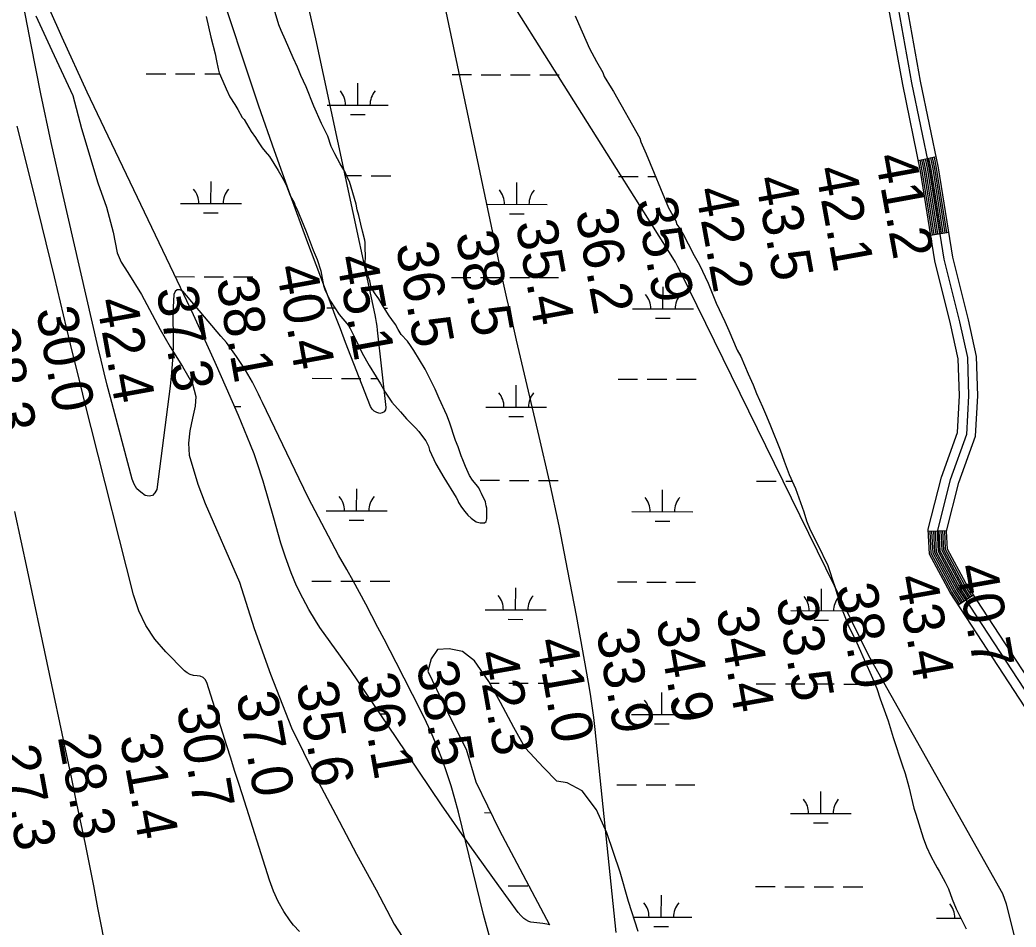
# Model space of a CAD drawing. Extents: x 3161665 to 3199565, y 885729 to 911164.
# Drawn here: x 3179018 to 3180653, y 894492 to 895980 of the extents above; entities that cross this region are included whole.
import ezdxf

# ---------------------------------------------------------------- set-up
doc = ezdxf.new("R2010")
doc.units = 0
for name, color, linetype in [('V-RIVR-RANG', 7, 'Continuous'), ('V-ROAD-CNTR', 7, 'Continuous'), ('V-SITE-VEGE', 7, 'Continuous'), ('V-TOPO-MAJR', 7, 'Continuous'), ('V-TOPO-MINR', 7, 'Continuous'), ('V-WETL-SWMP', 7, 'Continuous')]:
    doc.layers.add(name, color=color, linetype=linetype)

msp = doc.modelspace()

# ---------------------------------------------------------------- linework, layer by layer
at = {"layer": 'V-ROAD-CNTR'}
for p, q in [((3180492, 895749.5), (3180521.4, 895755.6)), ((3180512.4, 895626.9), (3180542, 895631.6)), ((3180508.4, 895141), (3180538.4, 895142.5)), ((3180557.4, 895020.5), (3180582.5, 895036.9))]:
    msp.add_line(p, q, dxfattribs=at)
for points in [[(3180933.2, 894493.7), (3180885, 894517.3), (3180701.9, 894799.4), (3180544.2, 895040.5), (3180510.3, 895103.5), (3180508.3, 895144.3), (3180530.1, 895229.9), (3180556.2, 895302.9), (3180559.6, 895363.6), (3180557.6, 895424.1), (3180545.1, 895481.1), (3180519.1, 895584.7), (3180495.6, 895731.9), (3180466.5, 895873.8), (3180444.2, 895996), (3180423.4, 896082.2), (3180408.8, 896168.2), (3180409.7, 896218.8), (3180409.8, 896281.3), (3180411, 896343.4), (3180408.4, 896411.6), (3180401.9, 896523.4)], [(3180416.8, 896524.3), (3180423.3, 896412.3), (3180426, 896343.5), (3180424.8, 896281.2), (3180424.7, 896218.6), (3180423.8, 896169.3), (3180438.1, 896085.2), (3180458.9, 895999.1), (3180481.2, 895876.7), (3180510.4, 895734.6), (3180533.8, 895587.7), (3180559.7, 895484.6), (3180572.6, 895426), (3180574.6, 895363.4), (3180571, 895299.9), (3180544.5, 895225.5), (3180523.4, 895142.8), (3180525.2, 895107.6), (3180557.1, 895048.2), (3180714.5, 894807.5), (3180895.4, 894528.9), (3180947.4, 894503.4), (3180964.9, 894492.4)], [(3180963.3, 894511.2), (3180954.7, 894516.5), (3180905.7, 894540.6), (3180727, 894815.7), (3180570.1, 895055.9), (3180540, 895111.8), (3180538.5, 895141.2), (3180558.9, 895221.1), (3180585.9, 895296.9), (3180589.7, 895363.3), (3180587.5, 895427.9), (3180574.3, 895488), (3180548.6, 895590.7), (3180525.2, 895737.3), (3180495.9, 895879.6), (3180473.6, 896002.2), (3180452.8, 896088.2), (3180438.9, 896170.4), (3180439.7, 896218.5), (3180439.8, 896281), (3180441, 896343.7), (3180438.3, 896413.1), (3180431.8, 896525.1)], [(3180515.4, 895627.4), (3180498.6, 895732.4), (3180495, 895750.1)], [(3180518.3, 895627.8), (3180501.5, 895733), (3180497.9, 895750.7)], [(3180521.3, 895628.3), (3180504.5, 895733.5), (3180500.8, 895751.3)], [(3180524.3, 895628.8), (3180507.5, 895734), (3180503.8, 895751.9)], [(3180527.2, 895629.3), (3180510.4, 895734.6), (3180506.7, 895752.5)], [(3180530.2, 895629.7), (3180513.4, 895735.1), (3180509.6, 895753.2)], [(3180533.1, 895630.2), (3180516.3, 895735.6), (3180512.6, 895753.8)], [(3180536.1, 895630.7), (3180519.3, 895736.2), (3180515.5, 895754.4)], [(3180539.1, 895631.1), (3180522.2, 895736.7), (3180518.5, 895755)], [(3180559.9, 895022.1), (3180546.8, 895042.1), (3180513.3, 895104.3), (3180511.4, 895141.1)], [(3180562.4, 895023.7), (3180549.4, 895043.6), (3180516.3, 895105.2), (3180514.4, 895141.3)], [(3180564.9, 895025.4), (3180552, 895045.1), (3180519.2, 895106), (3180517.4, 895141.5)], [(3180567.4, 895027), (3180554.6, 895046.7), (3180522.2, 895106.8), (3180520.4, 895141.6)], [(3180569.9, 895028.7), (3180557.1, 895048.2), (3180525.2, 895107.6), (3180523.4, 895141.8)], [(3180572.4, 895030.3), (3180559.7, 895049.8), (3180528.1, 895108.5), (3180526.4, 895141.9)], [(3180574.9, 895032), (3180562.3, 895051.3), (3180531.1, 895109.3), (3180529.4, 895142.1)], [(3180577.5, 895033.6), (3180564.9, 895052.8), (3180534, 895110.1), (3180532.4, 895142.2)], [(3180580, 895035.2), (3180567.5, 895054.4), (3180537, 895111), (3180535.4, 895142.4)]]:
    msp.add_lwpolyline(points, dxfattribs=at)
at = {"layer": 'V-SITE-VEGE'}
for p, q in [((3179043.8, 895986.4), (3179069.8, 895930)), ((3179069.8, 895930), (3179104.5, 895856.2)), ((3179104.5, 895856.2), (3179118.6, 895801.9)), ((3179118.6, 895801.9), (3179145.7, 895712.9)), ((3179145.7, 895712.9), (3179159.8, 895672.8)), ((3179159.8, 895672.8), (3179170.7, 895631.6)), ((3179170.7, 895631.6), (3179177.2, 895597.9)), ((3179177.2, 895597.9), (3179183.7, 895582.7)), ((3179183.7, 895582.7), (3179194.6, 895565.4)), ((3179194.6, 895565.4), (3179217.3, 895529.5)), ((3179217.3, 895529.5), (3179247.7, 895472)), ((3179247.7, 895472), (3179264, 895443.8)), ((3179264, 895443.8), (3179284.6, 895411.3)), ((3179284.6, 895411.3), (3179300.9, 895383.1)), ((3179300.9, 895383.1), (3179306.3, 895362.4)), ((3179306.3, 895362.4), (3179305.2, 895346.2)), ((3179305.2, 895346.2), (3179300.9, 895326.6)), ((3179300.9, 895326.6), (3179296.5, 895306)), ((3179296.5, 895306), (3179294.4, 895285.4)), ((3179294.4, 895285.4), (3179295.4, 895265.9)), ((3179295.4, 895265.9), (3179309.5, 895218.1)), ((3179309.5, 895218.1), (3179321.5, 895186.7)), ((3179321.5, 895186.7), (3179377.9, 895057.5)), ((3179377.9, 895057.5), (3179401.8, 894981.6)), ((3179401.8, 894981.6), (3179428.9, 894906.7)), ((3179428.9, 894906.7), (3179463.6, 894818.8)), ((3179463.6, 894818.8), (3179502.6, 894738.5)), ((3179502.6, 894738.5), (3179536.3, 894675.6)), ((3179536.3, 894675.6), (3179569.9, 894611.5)), ((3179569.9, 894611.5), (3179602.4, 894552.9)), ((3179602.4, 894552.9), (3179631.7, 894496.5)), ((3179631.7, 894496.5), (3179663.2, 894448.8))]:
    msp.add_line(p, q, dxfattribs=at)
at = {"layer": 'V-TOPO-MAJR'}
for points in [[(3179681.7, 896160.1), (3179801.4, 895592.2), (3179808.8, 895557.7), (3179816.4, 895523.4), (3179824.2, 895489), (3179832.1, 895454.7), (3179869.5, 895296.7), (3179886.1, 895223.5), (3179902, 895150.1), (3179916.6, 895076.4), (3179930.5, 895002.6), (3179950.1, 894893), (3179953.4, 894873.8), (3179956.3, 894854.6), (3179958.8, 894835.4), (3179961, 894816.1), (3179995.6, 894482.6)], [(3180681.8, 894350.6), (3180637, 894529.1), (3180631.1, 894546.5), (3180410.8, 894936.6), (3180101, 895567.5), (3180097.6, 895575.1), (3180093.7, 895582.5), (3180089.4, 895589.8), (3179777.1, 896084.7)], [(3179787.8, 894478.3), (3179778.7, 894512.5), (3179737.3, 894680.3), (3179731.5, 894701.9), (3179725.3, 894723.3), (3179718.3, 894744.6), (3179710.9, 894765.6), (3179702.7, 894786.4), (3179694, 894807), (3179684.7, 894827.3), (3179674.9, 894847.4), (3179634.9, 894925.9), (3179625, 894945.1), (3179615.2, 894964.3), (3179605.2, 894983.4), (3179595.2, 895002.5), (3179585.1, 895021.6), (3179574.8, 895040.6), (3179564.5, 895059.5), (3179554, 895078.4), (3179540.7, 895102.1), (3179523.8, 895133), (3179507.4, 895164), (3179491.4, 895195.4), (3179475.9, 895226.9), (3179415.6, 895352.3), (3179412.4, 895359), (3179409.2, 895365.7), (3179405.9, 895372.5), (3179402.6, 895379.2), (3179399.2, 895385.8), (3179395.7, 895392.4), (3179391.9, 895398.8), (3179388, 895405.2), (3179380.9, 895416.3), (3179373.1, 895427.9), (3179365, 895439.4), (3179356.5, 895450.5), (3179347.6, 895461.3), (3179285, 895534.7), (3179280.1, 895537), (3179275.8, 895537.3), (3179272.5, 895534.5), (3179270, 895529.7), (3179269.4, 895519.3), (3179269, 895508.8), (3179268.8, 895498.3), (3179268.8, 895487.8), (3179269.1, 895465.5), (3179269, 895443.8), (3179268.2, 895422.2), (3179266.5, 895400.7), (3179264.1, 895379.2), (3179242.1, 895209.8), (3179239.2, 895203.9), (3179235.2, 895199.9), (3179229.7, 895198.9), (3179223.1, 895199.9), (3179215.8, 895205), (3179209.6, 895210.9), (3179205.1, 895218.3), (3179201.8, 895226.5), (3179166.3, 895360.3), (3179161, 895380.7), (3179155.9, 895401.1), (3179150.9, 895421.5), (3179146.1, 895442), (3179086.8, 895699.1), (3179069, 895778.8), (3179052, 895858.7), (3179036, 895938.8), (3179020.7, 896019.1)]]:
    msp.add_lwpolyline(points, dxfattribs=at)
at = {"layer": 'V-TOPO-MINR'}
for points in [[(3179490.3, 896004.2), (3179502.5, 895948.9), (3179600.1, 895496.3), (3179601.3, 895490), (3179602.4, 895483.7), (3179603.3, 895477.4), (3179604.1, 895471.1), (3179618.2, 895344.3), (3179617.4, 895340.2), (3179615.6, 895337), (3179612.4, 895335.2), (3179608.3, 895334.4), (3179603.4, 895335.8), (3179599.2, 895338), (3179595.9, 895341.5), (3179593.2, 895345.9), (3179560.8, 895428.5), (3179552.2, 895450.7), (3179543.6, 895472.9), (3179535.1, 895495.1), (3179526.7, 895517.3), (3179488.6, 895618.6), (3179461.7, 895691.7), (3179435.3, 895765), (3179409.9, 895838.6), (3179385, 895912.4), (3179295.6, 896183.8)], [(3179476.3, 894484.6), (3179466.5, 894495.1), (3179461.4, 894501.9), (3179450.9, 894517.5), (3179441.5, 894533.7), (3179433.8, 894550.8), (3179427.2, 894568.5), (3179382.7, 894708.6), (3179376.3, 894728.7), (3179369.9, 894748.8), (3179363.5, 894769), (3179357.1, 894789.1), (3179324.1, 894893), (3179321.4, 894897.6), (3179318.1, 894901.2), (3179313.6, 894903.1), (3179308.4, 894904.1), (3179302.6, 894904.6), (3179297.2, 894906), (3179292.3, 894908.7), (3179287.8, 894912.2), (3179256.9, 894943.1), (3179239.2, 894963.9), (3179224, 894986.2), (3179212.6, 895010.7), (3179203.8, 895036.6), (3179134.5, 895311.4), (3179124.2, 895352.3), (3179114, 895393.3), (3179104, 895434.4), (3179094.1, 895475.4), (3179074.1, 895558.3), (3179054.1, 895640.8), (3179033.8, 895723.2), (3179013.1, 895805.5)], [(3179306.3, 893574), (3179246.9, 893954.3), (3179241.4, 893988.3), (3179235.9, 894022.2), (3179230, 894056.1), (3179224, 894089.9), (3179152.3, 894487.5), (3179145.6, 894523.4), (3179138.8, 894559.1), (3179131.7, 894594.9), (3179124.5, 894630.6), (3179117, 894666.2), (3179109.6, 894701.9), (3179102.1, 894737.5), (3179094.5, 894773.2), (3179030.2, 895077.4), (3179019.8, 895125.6), (3179009.2, 895173.7)]]:
    msp.add_lwpolyline(points, dxfattribs=at)
at = {"layer": 'V-WETL-SWMP'}
for p, q in [((3179224.9, 895891.6), (3179256.9, 895891.5)), ((3179272.9, 895891.5), (3179304.9, 895891.4)), ((3179320.9, 895891.4), (3179345.5, 895891.3)), ((3179726.8, 895890.2), (3179758.8, 895890.2)), ((3179774.8, 895890.1), (3179806.8, 895890)), ((3179822.8, 895890), (3179854.8, 895889.9)), ((3179870.8, 895889.9), (3179902.8, 895889.8)), ((3179572, 895839.9), (3179572.1, 895875.9)), ((3179522, 895840.1), (3179622, 895839.8)), ((3179560, 895824.5), (3179584, 895824.5)), ((3179554, 895724.6), (3179578.3, 895724.5)), ((3179594.3, 895724.4), (3179626.3, 895724.4)), ((3180000.2, 895723.3), (3180032.2, 895723.2)), ((3180048.2, 895723.2), (3180060.9, 895723.2)), ((3179331.1, 895678.7), (3179331.2, 895714.7)), ((3179833, 895677.4), (3179833.1, 895713.4)), ((3179281.1, 895678.9), (3179381.1, 895678.6)), ((3179783, 895677.5), (3179883, 895677.2)), ((3179319.1, 895663.3), (3179343.1, 895663.3)), ((3179821, 895662), (3179845, 895661.9)), ((3179272.9, 895558.8), (3179303.9, 895558.7)), ((3179319.9, 895558.7), (3179351.9, 895558.6)), ((3179367.9, 895558.6), (3179399.9, 895558.5)), ((3179725.8, 895557.6), (3179757.8, 895557.5)), ((3179773.8, 895557.4), (3179805.8, 895557.4)), ((3179821.8, 895557.3), (3179853.8, 895557.2)), ((3179869.8, 895557.2), (3179901.8, 895557.1)), ((3180073, 895505.9), (3180073.1, 895541.9)), ((3179521.1, 895507.4), (3179534.4, 895507.4)), ((3179615.6, 895507.1), (3179621.1, 895507.1)), ((3180023, 895506), (3180123, 895505.7)), ((3180061, 895490.5), (3180085, 895490.4)), ((3179497.4, 895392), (3179529.4, 895391.9)), ((3179545.4, 895391.9), (3179577.4, 895391.8)), ((3179593.4, 895391.8), (3179603.8, 895391.7)), ((3179999.3, 895390.6), (3180031.3, 895390.6)), ((3180047.3, 895390.5), (3180079.3, 895390.4)), ((3180095.3, 895390.4), (3180127.3, 895390.3)), ((3179832.1, 895344.7), (3179832.2, 895380.7)), ((3179369.7, 895346), (3179380.2, 895345.9)), ((3179782.1, 895344.8), (3179882.1, 895344.5)), ((3179820.1, 895329.3), (3179844.1, 895329.2)), ((3179570.2, 895174.6), (3179570.3, 895210.6)), ((3179772.9, 895224.8), (3179804.9, 895224.7)), ((3179820.9, 895224.6), (3179852.9, 895224.5)), ((3179868.9, 895224.5), (3179900.9, 895224.4)), ((3180226.8, 895223.5), (3180258.8, 895223.4)), ((3180274.8, 895223.4), (3180285.1, 895223.4)), ((3180072.1, 895173.2), (3180072.2, 895209.2)), ((3179520.2, 895174.7), (3179620.2, 895174.4)), ((3180022.1, 895173.3), (3180122.1, 895173.1)), ((3179558.1, 895159.2), (3179582.1, 895159.1)), ((3180060.1, 895157.8), (3180084.1, 895157.7)), ((3179496.5, 895059.4), (3179528.5, 895059.3)), ((3179544.5, 895059.2), (3179576.5, 895059.1)), ((3179592.5, 895059.1), (3179624.5, 895059)), ((3179831.2, 895012), (3179831.3, 895048)), ((3179998.4, 895058), (3180030.4, 895057.9)), ((3180046.4, 895057.8), (3180078.4, 895057.8)), ((3180094.4, 895057.7), (3180126.4, 895057.6)), ((3180333.1, 895010.6), (3180333.2, 895046.6)), ((3179781.2, 895012.1), (3179881.2, 895011.9)), ((3180283.1, 895010.8), (3180367.6, 895010.5)), ((3179819.1, 894996.6), (3179843.1, 894996.5)), ((3180321, 894995.2), (3180345, 894995.2)), ((3179788.7, 894892), (3179804, 894892)), ((3179820, 894892), (3179852, 894891.9)), ((3179868, 894891.8), (3179900, 894891.7)), ((3180225.9, 894890.8), (3180257.9, 894890.8)), ((3180273.9, 894890.7), (3180305.9, 894890.6)), ((3180321.9, 894890.6), (3180353.9, 894890.5)), ((3180369.9, 894890.4), (3180401.9, 894890.4)), ((3180071.2, 894840.5), (3180071.3, 894876.5)), ((3179608.7, 894841.8), (3179619.3, 894841.8)), ((3180021.2, 894840.7), (3180121.2, 894840.4)), ((3180059.1, 894825.1), (3180083.1, 894825.1)), ((3179997.5, 894725.3), (3180029.5, 894725.2)), ((3180045.5, 894725.2), (3180077.5, 894725.1)), ((3180093.5, 894725), (3180125.5, 894724.9)), ((3180332.2, 894677.9), (3180332.3, 894713.9)), ((3179780.3, 894679.5), (3179790.7, 894679.4)), ((3180282.2, 894678.1), (3180382.2, 894677.8)), ((3180320.1, 894662.5), (3180344.1, 894662.5)), ((3179819.1, 894559.3), (3179851.1, 894559.2)), ((3180225, 894558.2), (3180257, 894558.1)), ((3180273, 894558), (3180305, 894557.9)), ((3180321, 894557.9), (3180353, 894557.8)), ((3180369, 894557.8), (3180401, 894557.7)), ((3180070.3, 894507.9), (3180070.4, 894543.9)), ((3180024.9, 894508), (3180120.3, 894507.7)), ((3180522.2, 894506.6), (3180562, 894506.5)), ((3180058.2, 894492.5), (3180082.2, 894492.4))]:
    msp.add_line(p, q, dxfattribs=at)
for points in [[(3179780, 895155), (3179782.6, 895156.9), (3179783.9, 895161.4), (3179784, 895178.9), (3179782.8, 895182.8), (3179781.5, 895189.3), (3179775.1, 895203), (3179773.2, 895207.5), (3179770.7, 895212.1), (3179766.2, 895217.9), (3179760.4, 895225.1), (3179755.3, 895232.3), (3179748.9, 895247.2), (3179744.5, 895258.3), (3179741.9, 895264.8), (3179736.8, 895279.7), (3179732.4, 895290.1), (3179722.9, 895320), (3179718.4, 895331.7), (3179705.7, 895359), (3179699.3, 895374), (3179682.7, 895407.2), (3179664.1, 895437.8), (3179658.4, 895445.6), (3179653.9, 895452.7), (3179643.6, 895463.8), (3179638.5, 895472.3), (3179634, 895480.1), (3179628.2, 895488.6), (3179623.7, 895494.4), (3179614.1, 895509.4), (3179606.4, 895522.4), (3179603.9, 895526.3), (3179600.7, 895530.3), (3179596.8, 895536.8), (3179593.6, 895543.9), (3179591.8, 895551.7), (3179588.6, 895560.8), (3179584.2, 895580.9), (3179584.2, 895584.8), (3179584.9, 895588.1), (3179585, 895597.1), (3179584.3, 895601), (3179584.4, 895614.6), (3179583.8, 895618.5), (3179580.1, 895633.5), (3179576.9, 895645.1), (3179573.8, 895658.8), (3179571.2, 895668.5), (3179569.4, 895677.6), (3179558.6, 895714.6), (3179555.4, 895721.1), (3179551, 895731.5), (3179543.3, 895743.9), (3179534.3, 895760.2), (3179528.6, 895772.5), (3179522.9, 895789.4), (3179512.7, 895810.2), (3179499.9, 895838.2), (3179487.2, 895870.1), (3179478.9, 895888.9), (3179473.2, 895902.6), (3179466.2, 895917.5), (3179453.4, 895946.8), (3179446.4, 895962.4), (3179442.6, 895972.1), (3179423.6, 896036.4)], [(3179560.6, 894912.9), (3179510.1, 894983.1), (3179502.5, 894994.7), (3179492, 895012.7), (3179482, 895031.1), (3179471.8, 895051.8), (3179462.8, 895073), (3179453.3, 895098.8), (3179445.9, 895121.7), (3179434.1, 895162.3), (3179416.8, 895223.2), (3179407.2, 895253.3), (3179401.9, 895268.1), (3179396.1, 895282.8), (3179376.1, 895331), (3179356.8, 895375.9), (3179338.2, 895417.8), (3179302.5, 895496), (3179270.4, 895564.1), (3179156.2, 895801.7), (3179128, 895861.3), (3179086.8, 895951.2), (3179066.8, 895996.4)], [(3179323.4, 895985.3), (3179331, 895951.6), (3179337.9, 895924.3), (3179340.4, 895912.6), (3179342.9, 895899.7), (3179344.8, 895893.2), (3179346.7, 895888), (3179356.3, 895867.1), (3179362, 895853.5), (3179370.3, 895841.1), (3179375.4, 895832.7), (3179382.5, 895819.6), (3179385.7, 895816.4), (3179397.2, 895796.8), (3179404.3, 895787.1), (3179408.8, 895779.9), (3179415.2, 895770.1), (3179420.3, 895764.3), (3179427.4, 895755.8), (3179441.5, 895733), (3179449.8, 895718.7), (3179454.9, 895707.6), (3179461.2, 895692), (3179467.6, 895680.3), (3179469.5, 895675.1), (3179472.1, 895669.9), (3179487.4, 895632.9), (3179498.8, 895602.3), (3179505.2, 895586.7), (3179511.5, 895568.5), (3179515.9, 895544.5), (3179517.8, 895537.4), (3179521.6, 895529.6), (3179527.3, 895518.5), (3179541.4, 895496.4), (3179556.9, 895478.7), (3179559.4, 895473.5), (3179569, 895455.3), (3179579.2, 895433.2), (3179590.7, 895413), (3179602.2, 895394.2), (3179609.3, 895383.1), (3179617, 895369.4), (3179627.9, 895353.1), (3179642, 895336.8), (3179652.3, 895325.7), (3179667.1, 895310.7), (3179672.2, 895304.8), (3179678.6, 895296.4), (3179683.8, 895289.2), (3179688.2, 895280.7), (3179690.1, 895274.2), (3179700.3, 895251.5), (3179713.1, 895229.4), (3179733.6, 895196.2), (3179736.2, 895191.6), (3179737.4, 895188.3), (3179742.6, 895180.5), (3179747.7, 895173.4), (3179752.8, 895167.5), (3179758, 895162.3), (3179766.4, 895156.4), (3179772.8, 895155), (3179780, 895155)], [(3179928.8, 895986.7), (3179934.5, 895974.3), (3179952.3, 895933.3), (3179963.9, 895911.9), (3179974.1, 895893.6), (3179976.6, 895887.1), (3179988.2, 895868.3), (3179992, 895862.4), (3180034.9, 895786.2), (3180036.7, 895779.8), (3180045.7, 895760.2), (3180082, 895671.8), (3180094.1, 895650.4), (3180096, 895644.5), (3180100.5, 895638), (3180103.7, 895632.1), (3180105.6, 895629.5), (3180114.6, 895612.6), (3180124.1, 895593.7), (3180133.1, 895578.1), (3180147.1, 895548.2), (3180160.5, 895515.1), (3180174.5, 895485.1), (3180180.9, 895470.2), (3180194.9, 895438.3), (3180200.7, 895427.9), (3180212.8, 895399.3), (3180221.1, 895381.1), (3180226.8, 895366.8), (3180236.4, 895345.3), (3180242.7, 895329.7), (3180249.7, 895314.1), (3180265.6, 895274.5), (3180272, 895256.3), (3180280.2, 895234.2), (3180290.4, 895211.4), (3180304.4, 895173.1), (3180308.8, 895158.2), (3180314.6, 895143.2), (3180326.7, 895119.8), (3180343.9, 895084.7), (3180347.7, 895073.6), (3180351.5, 895061.3), (3180355.3, 895050.2), (3180358.5, 895039.2), (3180368, 895009.3), (3180377.5, 894985.9), (3180383.3, 894973.5), (3180389.7, 894961.8), (3180394.8, 894949.5), (3180403.1, 894930.6), (3180417.1, 894900.1), (3180424.1, 894883.1), (3180429.8, 894866.3), (3180442.5, 894829.9), (3180450.7, 894802.6), (3180465.9, 894757.8), (3180470.3, 894743.5), (3180476.7, 894722), (3180484.8, 894687), (3180488, 894677.2), (3180500, 894638.3), (3180505.7, 894623.3), (3180512.8, 894608.3), (3180519.8, 894594.7), (3180523, 894588.8), (3180526.2, 894583.6), (3180536.4, 894565.4), (3180541.5, 894554.3), (3180547.9, 894537.4), (3180554.2, 894521.8), (3180563.8, 894503), (3180570.8, 894488.7)], [(3180032.4, 894484.5), (3180016.6, 894533.9), (3180002.7, 894582), (3179981.1, 894646.3), (3179963.9, 894684), (3179940.2, 894715.3), (3179915.7, 894728.4), (3179898.8, 894731.2), (3179877, 894753.4), (3179846.7, 894786), (3179828.2, 894819.2), (3179806.5, 894860.2), (3179787.3, 894894.7), (3179763.6, 894928.5), (3179744.2, 894943.6), (3179722.2, 894948.3), (3179702.8, 894947.1), (3179692.3, 894931.7), (3179686.9, 894911.6), (3179723.3, 894836.8), (3179750.2, 894783.5), (3179766, 894730.2), (3179804.3, 894651.5), (3179886.7, 894495.4), (3179882.4, 894496.5), (3179875.7, 894497.5), (3179855.9, 894500), (3179852.9, 894500.9), (3179847.8, 894503.4), (3179844.4, 894505.9), (3179839.7, 894510.5), (3179835.6, 894515.4), (3179803.4, 894559.4), (3179756, 894625.5), (3179709.7, 894692.3), (3179635.2, 894802.7), (3179560.6, 894912.9)]]:
    msp.add_lwpolyline(points, dxfattribs=at)
for centre, start, end in [((3179516.8, 895840.6), 359.0698, 40.6135), ((3179627.3, 895840.3), 139.0698, 180.6135), ((3179275.9, 895679.4), 359.0698, 40.6135), ((3179386.4, 895679.1), 139.0698, 180.6135), ((3179777.8, 895678), 359.0698, 40.6135), ((3179888.3, 895677.7), 139.0698, 180.6135), ((3180017.8, 895506.5), 359.0698, 40.6135), ((3180128.3, 895506.2), 139.0698, 180.6135), ((3179776.9, 895345.3), 359.0698, 40.6135), ((3179887.3, 895345), 139.0698, 180.6135), ((3179515, 895175.2), 359.0698, 40.6135), ((3179625.4, 895174.9), 139.0698, 180.6135), ((3180016.9, 895173.8), 359.0698, 40.6135), ((3180127.3, 895173.5), 139.0698, 180.6135), ((3179775.9, 895012.6), 359.0698, 40.6135), ((3179886.4, 895012.3), 139.0698, 180.6135), ((3180277.8, 895011.2), 359.0698, 40.6135), ((3180388.3, 895010.9), 141.9632, 180.6135), ((3179624.5, 894842.2), 139.0698, 146.3078), ((3180015.9, 894841.2), 359.0698, 40.6135), ((3180126.4, 894840.8), 139.0698, 180.6135), ((3180276.9, 894678.6), 359.0698, 40.6135), ((3180387.4, 894678.3), 139.0698, 180.6135), ((3180015, 894508.5), 359.0698, 40.6135), ((3180125.5, 894508.2), 139.0698, 180.6135), ((3180516.9, 894507.1), 359.0698, 40.6135)]:
    msp.add_arc(centre, 35.2, start, end, dxfattribs=at)

# ---------------------------------------------------------------- texts
at = {"layer": 'V-RIVR-RANG'}
for s, rotation, p in [('41.2', 280.3483, (3180420.9, 895756)), ('42.1', 280.3483, (3180323, 895735.5)), ('43.5', 280.3483, (3180224.2, 895719.6)), ('42.2', 280.3483, (3180125.9, 895701.4)), ('35.9', 280.3483, (3180027.5, 895683.5)), ('36.2', 280.3483, (3179929.3, 895665)), ('35.4', 280.3483, (3179830.9, 895646.8)), ('38.5', 280.3483, (3179732.6, 895628.6)), ('36.5', 280.3483, (3179634.3, 895610.4)), ('45.1', 280.3483, (3179536.4, 895589.9)), ('40.4', 280.3483, (3179437.6, 895574)), ('38.1', 280.3483, (3179339.7, 895553.5)), ('37.3', 280.3483, (3179240.9, 895537.6)), ('42.4', 280.3483, (3179142.6, 895519.4)), ('30.0', 280.3483, (3179043.8, 895504.1)), ('28.3', 280.6283, (3178947.9, 895469.5)), ('40.7', 280.0783, (3180553.9, 895083.1)), ('43.4', 280.0783, (3180455.5, 895065.3)), ('38.0', 280.0783, (3180356.6, 895050.4)), ('33.5', 280.0783, (3180258.6, 895029.8)), ('34.4', 280.0783, (3180160.2, 895012.1)), ('34.9', 280.0783, (3180061.8, 894994.6)), ('33.9', 280.0783, (3179963.4, 894976.8)), ('41.0', 280.0783, (3179864.5, 894961.7)), ('42.3', 280.0783, (3179766.6, 894941.1)), ('38.5', 280.0783, (3179668.2, 894923.3)), ('36.1', 280.0783, (3179570.2, 894903.3)), ('35.6', 280.0783, (3179471, 894889.7)), ('37.0', 280.0783, (3179372.4, 894873)), ('30.7', 280.0783, (3179274.5, 894852.3)), ('28.3', 280.3581, (3179079.6, 894803.4)), ('31.4', 280.3581, (3179181.2, 894803.7)), ('27.3', 280.3581, (3178981.3, 894785.1))]:
    msp.add_text(s, height=67, rotation=rotation, dxfattribs=at).set_placement(p)

doc.saveas('drawing.dxf')
